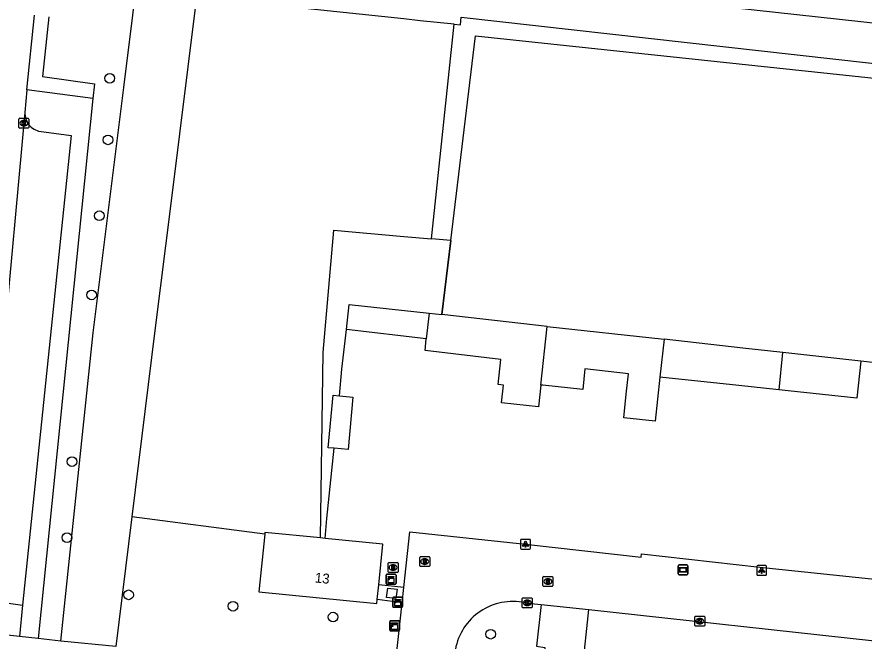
# Model space of a CAD drawing. Extents: x 162515 to 163909, y 388494 to 389773.
# Drawn here: x 162960.9 to 163046.5, y 388555.4 to 388618.6 of the extents above; entities that cross this region are included whole.
import ezdxf

# ---------------------------------------------------------------- set-up
doc = ezdxf.new("R2010")
doc.units = 0
for name, color, linetype in [('IMGEO_Boom', 7, 'Continuous'), ('IMGEO_Groenvoorziening', 7, 'Continuous'), ('IMGEO_Hek', 7, 'Continuous'), ('IMGEO_Kast', 7, 'Continuous'), ('IMGEO_Kolk', 7, 'Continuous'), ('IMGEO_Lage_trafo', 7, 'Continuous'), ('IMGEO_Lichtpunt', 7, 'Continuous'), ('IMGEO_Loofbos', 7, 'Continuous'), ('IMGEO_Pand', 7, 'Continuous'), ('IMGEO_Pand_nummerreeks', 7, 'Continuous'), ('IMGEO_Parkeervlak_open', 7, 'Continuous'), ('IMGEO_Rijbaan_lokaal_open', 7, 'Continuous'), ('IMGEO_Rioolput', 7, 'Continuous'), ('IMGEO_Terreindeel_open', 7, 'Continuous'), ('IMGEO_Verklikker', 7, 'Continuous'), ('IMGEO_Voetpad_onverhard', 7, 'Continuous'), ('IMGEO_Voetpad_open', 7, 'Continuous')]:
    doc.layers.add(name, color=color, linetype=linetype)

msp = doc.modelspace()

# ---------------------------------------------------------------- linework, layer by layer
at = {"layer": 'IMGEO_Boom'}
for centre in [(162970.262, 388612.35), (162970.081, 388606.124), (162969.213, 388598.45), (162968.421, 388590.446), (162966.439, 388573.592), (162965.943, 388565.899), (162972.163, 388560.113), (162982.721, 388558.962), (162992.839, 388557.86), (163008.769, 388556.133)]:
    msp.add_circle(centre, 0.489, dxfattribs=at)
at = {"layer": 'IMGEO_Groenvoorziening'}
for points in [[(163004.733, 388595.939), (163007.23, 388616.641), (163090.354, 388607.805), (163079.489, 388585.494)], [(163004.733, 388595.939), (163002.79, 388596.108)], [(163003.829, 388588.448), (163004.733, 388595.939)], [(162993.498, 388580.23), (162993.73, 388582.932), (162994.196, 388586.945)], [(163050.343, 388583.278), (163046.197, 388583.746)], [(162992.026, 388565.819), (162992.203, 388567.817), (162992.946, 388574.941)], [(162999.817, 388559.316), (162997.301, 388559.633)]]:
    msp.add_lwpolyline(points, dxfattribs=at)
at = {"layer": 'IMGEO_Hek'}
for points in [[(163005.069, 388617.81), (163001.65, 388618.175), (163000, 388618.351), (162979.016, 388620.588), (162976.424, 388599.705), (162974.828, 388586.841), (162972.488, 388567.987)], [(163002.79, 388596.108), (163005.069, 388617.81)], [(163004.733, 388595.939), (163003.829, 388588.448)], [(162972.488, 388567.987), (162970.86, 388554.877)]]:
    msp.add_lwpolyline(points, dxfattribs=at)
at = {"layer": 'IMGEO_Kast'}
for p, q in [((162998.198, 388561.264), (162998.198, 388562.105)), ((162998.198, 388562.105), (162998.198, 388561.264)), ((162998.273, 388562.189), (162999.114, 388562.189)), ((162999.114, 388562.189), (162998.273, 388562.189)), ((162999.198, 388562.114), (162999.198, 388561.273)), ((162999.198, 388561.273), (162999.198, 388562.114)), ((162999.123, 388561.189), (162998.282, 388561.189)), ((162998.282, 388561.189), (162999.123, 388561.189)), ((162998.868, 388558.936), (162998.868, 388559.777)), ((162998.868, 388559.777), (162998.868, 388558.936)), ((162998.943, 388559.861), (162999.784, 388559.861)), ((162999.784, 388559.861), (162998.943, 388559.861)), ((162999.868, 388559.786), (162999.868, 388558.945)), ((162999.868, 388558.945), (162999.868, 388559.786)), ((162999.793, 388558.861), (162998.952, 388558.861)), ((162998.952, 388558.861), (162999.793, 388558.861)), ((162998.563, 388556.557), (162998.563, 388557.398)), ((162998.563, 388557.398), (162998.563, 388556.557)), ((162998.638, 388557.482), (162999.479, 388557.482)), ((162999.479, 388557.482), (162998.638, 388557.482)), ((162999.563, 388557.407), (162999.563, 388556.566)), ((162999.563, 388556.566), (162999.563, 388557.407)), ((162999.488, 388556.482), (162998.647, 388556.482)), ((162998.647, 388556.482), (162999.488, 388556.482))]:
    msp.add_line(p, q, dxfattribs=at)
for points in [[(162998.393, 388561.979), (162998.993, 388561.979), (162998.993, 388561.894), (162998.393, 388561.894), (162998.393, 388561.979)], [(162998.393, 388561.804), (162998.993, 388561.804), (162998.993, 388561.315), (162998.393, 388561.315), (162998.393, 388561.804)], [(162999.063, 388559.651), (162999.663, 388559.651), (162999.663, 388559.566), (162999.063, 388559.566), (162999.063, 388559.651)], [(162999.063, 388559.476), (162999.663, 388559.476), (162999.663, 388558.987), (162999.063, 388558.987), (162999.063, 388559.476)], [(162998.758, 388557.272), (162999.358, 388557.272), (162999.358, 388557.187), (162998.758, 388557.187), (162998.758, 388557.272)], [(162998.758, 388557.097), (162999.358, 388557.097), (162999.358, 388556.608), (162998.758, 388556.608), (162998.758, 388557.097)]]:
    msp.add_lwpolyline(points, dxfattribs=at)
for centre in [(162998.477, 388561.653), (162999.147, 388559.325), (162998.842, 388556.946)]:
    msp.add_circle(centre, 0.0377, dxfattribs=at)
for centre, start, end in [((162998.276, 388562.111), 92.4484, 184.28452), ((162998.276, 388562.111), 92.4484, 184.28452), ((162999.12, 388562.111), 2.4484, 94.28452), ((162999.12, 388562.111), 2.4484, 94.28452), ((162998.276, 388561.267), 182.4484, 274.28452), ((162998.276, 388561.267), 182.4484, 274.28452), ((162999.12, 388561.267), 272.4484, 4.28452), ((162999.12, 388561.267), 272.4484, 4.28452), ((162998.946, 388559.783), 92.4484, 184.28452), ((162998.946, 388559.783), 92.4484, 184.28452), ((162999.79, 388559.783), 2.4484, 94.28452), ((162999.79, 388559.783), 2.4484, 94.28452), ((162998.946, 388558.939), 182.4484, 274.28452), ((162998.946, 388558.939), 182.4484, 274.28452), ((162999.79, 388558.939), 272.4484, 4.28452), ((162999.79, 388558.939), 272.4484, 4.28452), ((162998.641, 388557.404), 92.4484, 184.28452), ((162998.641, 388557.404), 92.4484, 184.28452), ((162999.485, 388557.404), 2.4484, 94.28452), ((162999.485, 388557.404), 2.4484, 94.28452), ((162998.641, 388556.56), 182.4484, 274.28452), ((162998.641, 388556.56), 182.4484, 274.28452), ((162999.485, 388556.56), 272.4484, 4.28452), ((162999.485, 388556.56), 272.4484, 4.28452)]:
    msp.add_arc(centre, 0.0779, start, end, dxfattribs=at)
at = {"layer": 'IMGEO_Kolk'}
for p, q in [((162961.079, 388607.383), (162961.079, 388608.235)), ((162961.154, 388608.309), (162962.006, 388608.309)), ((162961.567, 388608.089), (162961.592, 388608.089)), ((162962.08, 388608.235), (162962.08, 388607.383)), ((162962.006, 388607.309), (162961.154, 388607.309)), ((162961.59, 388607.529), (162961.565, 388607.529)), ((163011.965, 388558.876), (163011.965, 388559.728)), ((163012.04, 388559.802), (163012.892, 388559.802)), ((163012.966, 388559.728), (163012.966, 388558.876)), ((163012.476, 388559.022), (163012.451, 388559.022)), ((163012.453, 388559.582), (163012.478, 388559.582)), ((163012.892, 388558.802), (163012.04, 388558.802)), ((163029.411, 388557.023), (163029.411, 388557.875)), ((163029.486, 388557.949), (163030.338, 388557.949)), ((163029.922, 388557.169), (163029.897, 388557.169)), ((163029.899, 388557.729), (163029.924, 388557.729)), ((163030.412, 388557.875), (163030.412, 388557.023)), ((163030.338, 388556.949), (163029.486, 388556.949))]:
    msp.add_line(p, q, dxfattribs=at)
for points in [[(162961.079, 388607.383), (162961.079, 388608.235)], [(162961.154, 388608.309), (162962.006, 388608.309)], [(162961.4, 388608.009), (162961.523, 388608.009), (162961.523, 388607.858), (162961.653, 388608.009), (162961.817, 388608.009), (162961.671, 388607.858), (162961.824, 388607.609), (162961.672, 388607.609), (162961.587, 388607.773), (162961.523, 388607.706), (162961.523, 388607.609), (162961.4, 388607.609), (162961.4, 388608.009)], [(162962.08, 388608.235), (162962.08, 388607.383)], [(162962.006, 388607.309), (162961.154, 388607.309)], [(163011.965, 388558.876), (163011.965, 388559.728)], [(163012.04, 388559.802), (163012.892, 388559.802)], [(163012.966, 388559.728), (163012.966, 388558.876)], [(163012.286, 388559.502), (163012.409, 388559.502), (163012.409, 388559.351), (163012.539, 388559.502), (163012.703, 388559.502), (163012.557, 388559.351), (163012.71, 388559.102), (163012.558, 388559.102), (163012.473, 388559.266), (163012.409, 388559.199), (163012.409, 388559.102), (163012.286, 388559.102), (163012.286, 388559.502)], [(163012.892, 388558.802), (163012.04, 388558.802)], [(163029.411, 388557.023), (163029.411, 388557.875)], [(163029.486, 388557.949), (163030.338, 388557.949)], [(163029.732, 388557.649), (163029.855, 388557.649), (163029.855, 388557.498), (163029.985, 388557.649), (163030.149, 388557.649), (163030.003, 388557.498), (163030.156, 388557.249), (163030.004, 388557.249), (163029.919, 388557.413), (163029.855, 388557.346), (163029.855, 388557.249), (163029.732, 388557.249), (163029.732, 388557.649)], [(163030.412, 388557.875), (163030.412, 388557.023)], [(163030.338, 388556.949), (163029.486, 388556.949)]]:
    msp.add_lwpolyline(points, dxfattribs=at)
for centre, start, end in [((162961.156, 388608.233), 91.55205, 178.44795), ((162961.156, 388608.233), 91.55205, 178.44795), ((162962.004, 388608.233), 1.55205, 88.44795), ((162962.004, 388608.233), 1.55205, 88.44795), ((162961.156, 388607.385), 181.55205, 268.44795), ((162961.156, 388607.385), 181.55205, 268.44795), ((162962.004, 388607.385), 271.55205, 358.44795), ((162962.004, 388607.385), 271.55205, 358.44795), ((163012.042, 388559.726), 91.55205, 178.44795), ((163012.042, 388559.726), 91.55205, 178.44795), ((163012.89, 388559.726), 1.55205, 88.44795), ((163012.89, 388559.726), 1.55205, 88.44795), ((163012.042, 388558.878), 181.55205, 268.44795), ((163012.042, 388558.878), 181.55205, 268.44795), ((163012.89, 388558.878), 271.55205, 358.44795), ((163012.89, 388558.878), 271.55205, 358.44795), ((163029.488, 388557.873), 91.55205, 178.44795), ((163029.488, 388557.873), 91.55205, 178.44795), ((163030.336, 388557.873), 1.55205, 88.44795), ((163030.336, 388557.873), 1.55205, 88.44795), ((163029.488, 388557.025), 181.55205, 268.44795), ((163029.488, 388557.025), 181.55205, 268.44795), ((163030.336, 388557.025), 271.55205, 358.44795), ((163030.336, 388557.025), 271.55205, 358.44795)]:
    msp.add_arc(centre, 0.0765, start, end, dxfattribs=at)
for centre, major_axis, ratio, start_param, end_param in [((162961.566, 388607.809), (-0.387, 0.002), 0.722429, 4.712389, 7.853982), ((162961.591, 388607.809), (-0.39, 0.002), 0.717154, 1.570796, 4.712389), ((163012.452, 388559.302), (-0.387, 0.002), 0.722429, 4.712389, 7.853982), ((163012.477, 388559.302), (-0.39, 0.002), 0.717154, 1.570796, 4.712389), ((163029.898, 388557.449), (-0.387, 0.002), 0.722429, 4.712389, 7.853982), ((163029.923, 388557.449), (-0.39, 0.002), 0.717154, 1.570796, 4.712389)]:
    msp.add_ellipse(centre, major_axis=major_axis, ratio=ratio, start_param=start_param, end_param=end_param, dxfattribs=at)
at = {"layer": 'IMGEO_Lage_trafo'}
msp.add_lwpolyline([(162999.194, 388559.753), (162998.254, 388559.859), (162998.36, 388560.799), (162999.3, 388560.693), (162999.194, 388559.753)], dxfattribs=at)
at = {"layer": 'IMGEO_Lichtpunt'}
for p, q in [((163012.692, 388565.722), (163011.884, 388565.722)), ((163012.692, 388565.722), (163011.884, 388565.722)), ((163011.79, 388565.627), (163011.79, 388564.82)), ((163011.79, 388565.627), (163011.79, 388564.82)), ((163012.786, 388564.82), (163012.786, 388565.627)), ((163012.786, 388564.82), (163012.786, 388565.627)), ((163011.884, 388564.726), (163012.692, 388564.726)), ((163011.884, 388564.726), (163012.692, 388564.726)), ((163035.667, 388562.988), (163035.667, 388562.181)), ((163035.667, 388562.988), (163035.667, 388562.181)), ((163036.569, 388563.083), (163035.761, 388563.083)), ((163036.569, 388563.083), (163035.761, 388563.083)), ((163036.663, 388562.181), (163036.663, 388562.988)), ((163036.663, 388562.181), (163036.663, 388562.988)), ((163035.761, 388562.087), (163036.569, 388562.087)), ((163035.761, 388562.087), (163036.569, 388562.087))]:
    msp.add_line(p, q, dxfattribs=at)
for points in [[(163012.164, 388565.291), (163012.203, 388565.263), (163012.015, 388565.001), (163011.977, 388565.028), (163012.164, 388565.291)], [(163012.266, 388565.243), (163012.313, 388565.243), (163012.313, 388564.921), (163012.266, 388564.921), (163012.266, 388565.243)], [(163012.376, 388565.263), (163012.414, 388565.29), (163012.601, 388565.028), (163012.562, 388565), (163012.376, 388565.263)], [(163036.041, 388562.652), (163036.08, 388562.624), (163035.892, 388562.362), (163035.854, 388562.389), (163036.041, 388562.652)], [(163036.143, 388562.604), (163036.19, 388562.604), (163036.19, 388562.282), (163036.143, 388562.282), (163036.143, 388562.604)], [(163036.253, 388562.624), (163036.291, 388562.651), (163036.478, 388562.389), (163036.439, 388562.361), (163036.253, 388562.624)]]:
    msp.add_lwpolyline(points, dxfattribs=at)
for centre in [(163012.289, 388565.425), (163036.166, 388562.786)]:
    msp.add_circle(centre, 0.0994, dxfattribs=at)
for centre, start, end in [((163011.884, 388565.627), 90, 180), ((163011.884, 388565.627), 90, 180), ((163012.692, 388565.627), 0, 90), ((163012.692, 388565.627), 0, 90), ((163011.884, 388564.82), 180, 270), ((163011.884, 388564.82), 180, 270), ((163012.692, 388564.82), 270, 0), ((163012.692, 388564.82), 270, 360), ((163035.761, 388562.988), 90, 180), ((163035.761, 388562.988), 90, 180), ((163036.569, 388562.988), 0, 90), ((163036.569, 388562.988), 0, 90), ((163035.761, 388562.181), 180, 270), ((163035.761, 388562.181), 180, 270), ((163036.569, 388562.181), 270, 0), ((163036.569, 388562.181), 270, 360)]:
    msp.add_arc(centre, 0.0946, start, end, dxfattribs=at)
at = {"layer": 'IMGEO_Loofbos'}
for points in [[(162964.118, 388618.562), (162963.448, 388612.545), (162968.731, 388611.807), (162968.549, 388610.318)], [(163002.79, 388596.108), (163005.069, 388617.81)], [(162991.571, 388565.865), (162991.826, 388584.623), (162992.929, 388596.983), (163000, 388596.356), (163002.79, 388596.108)], [(162985.926, 388566.254), (162972.488, 388567.987)]]:
    msp.add_lwpolyline(points, dxfattribs=at)
at = {"layer": 'IMGEO_Pand'}
for points in [[(162994.196, 388586.945), (162994.478, 388589.486), (163002.555, 388588.59)], [(163002.555, 388588.59), (163002.264, 388586.008)], [(163002.555, 388588.59), (163003.829, 388588.448)], [(163014.493, 388587.265), (163003.829, 388588.448)], [(163013.84, 388581.331), (163014.493, 388587.265)], [(163014.493, 388587.265), (163026.294, 388585.955)], [(163002.264, 388586.008), (162994.196, 388586.945)], [(163013.84, 388581.331), (163013.598, 388579.132), (163009.859, 388579.527), (163010.049, 388581.324), (163009.52, 388581.38), (163009.789, 388583.926), (163002.132, 388584.836), (163002.264, 388586.008)], [(163026.294, 388585.955), (163025.885, 388582.139)], [(163038.315, 388584.621), (163034.251, 388585.072), (163026.294, 388585.955)], [(163037.931, 388580.847), (163038.315, 388584.621)], [(163046.197, 388583.746), (163038.315, 388584.621)], [(163046.197, 388583.746), (163045.793, 388579.998), (163038.848, 388580.748), (163037.931, 388580.847)], [(163025.885, 388582.139), (163025.405, 388577.665), (163022.214, 388578.016), (163022.476, 388580.395), (163022.704, 388582.469), (163018.301, 388582.953), (163018.071, 388580.865), (163014.052, 388581.308), (163013.84, 388581.331)], [(163037.931, 388580.847), (163037.908, 388580.849), (163033.849, 388581.284), (163025.885, 388582.139)], [(162992.946, 388574.941), (162992.355, 388574.994), (162992.829, 388580.29), (162993.498, 388580.23)], [(162993.498, 388580.23), (162994.821, 388580.112), (162994.347, 388574.816), (162992.946, 388574.941)], [(162985.926, 388566.254), (162985.319, 388560.432), (162997.261, 388559.233), (162997.301, 388559.633)], [(162991.571, 388565.865), (162985.944, 388566.429), (162985.926, 388566.254)], [(162992.026, 388565.819), (162991.571, 388565.865)], [(162997.448, 388561.109), (162997.858, 388565.235), (162992.026, 388565.819)], [(162997.301, 388559.633), (162997.448, 388561.109)]]:
    msp.add_lwpolyline(points, dxfattribs=at)
at = {"layer": 'IMGEO_Parkeervlak_open'}
msp.add_lwpolyline([(162958.379, 388559.517), (162961.44, 388559.076)], dxfattribs=at)
at = {"layer": 'IMGEO_Rijbaan_lokaal_open'}
for points in [[(162961.889, 388611.173), (162962.649, 388618.722)], [(162961.889, 388611.173), (162961.68, 388608.905)], [(162961.68, 388608.905), (162959.411, 388584.283), (162956.595, 388558.931)], [(162999.987, 388560.86), (163000.607, 388566.496), (163012.283, 388565.224), (163023.98, 388563.913), (163024.016, 388564.261), (163035.984, 388562.926), (163047.901, 388561.655), (163059.732, 388560.275)], [(162999.817, 388559.316), (162999.987, 388560.86)], [(162998.998, 388551.886), (162999.817, 388559.316)], [(163012.22, 388559.314), (163013.862, 388559.137)], [(163013.862, 388559.137), (163018.69, 388558.618)], [(163018.69, 388558.618), (163047.561, 388555.463)]]:
    msp.add_lwpolyline(points, dxfattribs=at)
msp.add_arc((163011.007, 388553.534), 5.906, 78.15108, 169.67972, dxfattribs=at)
at = {"layer": 'IMGEO_Rioolput'}
for p, q in [((162998.401, 388562.454), (162998.401, 388563.306)), ((162998.476, 388563.38), (162999.328, 388563.38)), ((162998.889, 388563.16), (162998.914, 388563.16)), ((162999.402, 388563.306), (162999.402, 388562.454)), ((163001.607, 388563.05), (163001.607, 388563.902)), ((163001.682, 388563.976), (163002.534, 388563.976)), ((163002.118, 388563.196), (163002.093, 388563.196)), ((163002.095, 388563.756), (163002.12, 388563.756)), ((163002.608, 388563.902), (163002.608, 388563.05)), ((162999.328, 388562.38), (162998.476, 388562.38)), ((162998.912, 388562.6), (162998.887, 388562.6)), ((163002.534, 388562.976), (163001.682, 388562.976)), ((163014.054, 388561.042), (163014.054, 388561.894)), ((163014.129, 388561.968), (163014.981, 388561.968)), ((163014.542, 388561.748), (163014.567, 388561.748)), ((163015.055, 388561.894), (163015.055, 388561.042)), ((163014.981, 388560.968), (163014.129, 388560.968)), ((163014.565, 388561.188), (163014.54, 388561.188))]:
    msp.add_line(p, q, dxfattribs=at)
for points in [[(162998.401, 388562.454), (162998.401, 388563.306)], [(162998.476, 388563.38), (162999.328, 388563.38)], [(162999.402, 388563.306), (162999.402, 388562.454)], [(163001.607, 388563.05), (163001.607, 388563.902)], [(163001.682, 388563.976), (163002.534, 388563.976)], [(163002.196, 388563.674), (163001.944, 388563.676), (163001.944, 388563.276)], [(163001.944, 388563.276), (163002.068, 388563.276), (163002.068, 388563.438), (163002.079, 388563.438)], [(163002.122, 388563.595), (163002.068, 388563.595), (163002.068, 388563.514)], [(163002.068, 388563.514), (163002.12, 388563.514)], [(163002.126, 388563.409), (163002.197, 388563.276), (163002.337, 388563.276), (163002.272, 388563.402)], [(163002.608, 388563.902), (163002.608, 388563.05)], [(162999.328, 388562.38), (162998.476, 388562.38)], [(162998.99, 388563.078), (162998.738, 388563.08), (162998.738, 388562.68)], [(162998.738, 388562.68), (162998.862, 388562.68), (162998.862, 388562.842), (162998.873, 388562.842)], [(162998.916, 388562.999), (162998.862, 388562.999), (162998.862, 388562.918)], [(162998.862, 388562.918), (162998.914, 388562.918)], [(162998.92, 388562.813), (162998.991, 388562.68), (162999.131, 388562.68), (162999.066, 388562.806)], [(163002.534, 388562.976), (163001.682, 388562.976)], [(163014.054, 388561.042), (163014.054, 388561.894)], [(163014.129, 388561.968), (163014.981, 388561.968)], [(163014.643, 388561.666), (163014.391, 388561.668), (163014.391, 388561.268)], [(163014.391, 388561.268), (163014.515, 388561.268), (163014.515, 388561.43), (163014.526, 388561.43)], [(163014.569, 388561.587), (163014.515, 388561.587), (163014.515, 388561.506)], [(163014.515, 388561.506), (163014.567, 388561.506)], [(163015.055, 388561.894), (163015.055, 388561.042)], [(163014.981, 388560.968), (163014.129, 388560.968)], [(163014.573, 388561.401), (163014.644, 388561.268), (163014.784, 388561.268), (163014.719, 388561.394)]]:
    msp.add_lwpolyline(points, dxfattribs=at)
for centre, radius, start, end in [((162998.478, 388563.304), 0.0765, 91.55205, 178.44795), ((162998.478, 388563.304), 0.0765, 91.55205, 178.44795), ((162999.326, 388563.304), 0.0765, 1.55205, 88.44795), ((162999.326, 388563.304), 0.0765, 1.55205, 88.44795), ((163001.684, 388563.9), 0.0765, 91.55205, 178.44795), ((163001.684, 388563.9), 0.0765, 91.55205, 178.44795), ((163002.078, 388563.385), 0.0533, 26.02933, 88.69889), ((163002.104, 388563.703), 0.19, 274.7715, 282.96867), ((163002.128, 388563.499), 0.0964, 77.00612, 93.18647), ((163002.142, 388563.556), 0.0378, 276.66336, 79.67722), ((163002.195, 388563.564), 0.109, 350.36119, 89.41601), ((163002.193, 388563.564), 0.112, 277.58423, 350.98172), ((163002.177, 388563.349), 0.108, 29.51342, 73.79051), ((163002.532, 388563.9), 0.0765, 1.55205, 88.44795), ((163002.532, 388563.9), 0.0765, 1.55205, 88.44795), ((162998.478, 388562.456), 0.0765, 181.55205, 268.44795), ((162998.478, 388562.456), 0.0765, 181.55205, 268.44795), ((162998.872, 388562.789), 0.0533, 26.02933, 88.69889), ((162998.898, 388563.107), 0.19, 274.7715, 282.96867), ((162998.922, 388562.903), 0.0964, 77.00612, 93.18647), ((162998.936, 388562.96), 0.0378, 276.66336, 79.67722), ((162998.989, 388562.968), 0.109, 350.36119, 89.41601), ((162998.987, 388562.968), 0.112, 277.58423, 350.98172), ((162998.971, 388562.753), 0.108, 29.51342, 73.79051), ((162999.326, 388562.456), 0.0765, 271.55205, 358.44795), ((162999.326, 388562.456), 0.0765, 271.55205, 358.44795), ((163001.684, 388563.052), 0.0765, 181.55205, 268.44795), ((163001.684, 388563.052), 0.0765, 181.55205, 268.44795), ((163002.532, 388563.052), 0.0765, 271.55205, 358.44795), ((163002.532, 388563.052), 0.0765, 271.55205, 358.44795), ((163014.131, 388561.892), 0.0765, 91.55205, 178.44795), ((163014.131, 388561.892), 0.0765, 91.55205, 178.44795), ((163014.525, 388561.377), 0.0533, 26.02933, 88.69889), ((163014.551, 388561.695), 0.19, 274.7715, 282.96867), ((163014.575, 388561.491), 0.0964, 77.00612, 93.18647), ((163014.589, 388561.548), 0.0378, 276.66336, 79.67722), ((163014.642, 388561.556), 0.109, 350.36119, 89.41601), ((163014.64, 388561.556), 0.112, 277.58423, 350.98172), ((163014.624, 388561.341), 0.108, 29.51342, 73.79051), ((163014.979, 388561.892), 0.0765, 1.55205, 88.44795), ((163014.979, 388561.892), 0.0765, 1.55205, 88.44795), ((163014.131, 388561.044), 0.0765, 181.55205, 268.44795), ((163014.131, 388561.044), 0.0765, 181.55205, 268.44795), ((163014.979, 388561.044), 0.0765, 271.55205, 358.44795), ((163014.979, 388561.044), 0.0765, 271.55205, 358.44795)]:
    msp.add_arc(centre, radius, start, end, dxfattribs=at)
for centre, major_axis, ratio, start_param, end_param in [((162998.888, 388562.88), (-0.387, 0.002), 0.722429, 4.712389, 7.853982), ((162998.913, 388562.88), (-0.39, 0.002), 0.717154, 1.570796, 4.712389), ((163002.094, 388563.476), (-0.387, 0.002), 0.722429, 4.712389, 7.853982), ((163002.119, 388563.476), (-0.39, 0.002), 0.717154, 1.570796, 4.712389), ((163014.541, 388561.468), (-0.387, 0.002), 0.722429, 4.712389, 7.853982), ((163014.566, 388561.468), (-0.39, 0.002), 0.717154, 1.570796, 4.712389)]:
    msp.add_ellipse(centre, major_axis=major_axis, ratio=ratio, start_param=start_param, end_param=end_param, dxfattribs=at)
at = {"layer": 'IMGEO_Terreindeel_open'}
msp.add_lwpolyline([(162999.987, 388560.86), (162997.448, 388561.109)], dxfattribs=at)
at = {"layer": 'IMGEO_Verklikker'}
for p, q in [((163027.812, 388563.146), (163028.602, 388563.146)), ((163028.602, 388563.146), (163027.812, 388563.146)), ((163027.712, 388562.246), (163027.712, 388563.046)), ((163027.712, 388563.046), (163027.712, 388562.246)), ((163028.702, 388563.046), (163028.702, 388562.246)), ((163028.702, 388562.246), (163028.702, 388563.046)), ((163028.602, 388562.146), (163027.812, 388562.146)), ((163027.812, 388562.146), (163028.602, 388562.146))]:
    msp.add_line(p, q, dxfattribs=at)
for points in [[(163027.813, 388562.878), (163028.601, 388562.878), (163028.601, 388562.414), (163027.813, 388562.414), (163027.813, 388562.878)], [(163027.878, 388562.813), (163027.878, 388562.479), (163028.536, 388562.479), (163028.536, 388562.813), (163027.878, 388562.813)]]:
    msp.add_lwpolyline(points, dxfattribs=at)
for centre, start, end in [((163027.812, 388563.046), 90, 180), ((163027.812, 388563.046), 90, 180), ((163028.602, 388563.046), 0, 90), ((163028.602, 388563.046), 360, 90), ((163027.812, 388562.246), 180, 270), ((163027.812, 388562.246), 180, 270), ((163028.602, 388562.246), 270, 0), ((163028.602, 388562.246), 270, 0)]:
    msp.add_arc(centre, 0.1, start, end, dxfattribs=at)
at = {"layer": 'IMGEO_Voetpad_onverhard'}
for points in [[(162965.32, 388555.442), (162968.591, 388586.594), (162971.679, 388611.418), (162973.501, 388626.071), (163066.203, 388615.891), (163091.913, 388612.689), (163095.764, 388613.06)], [(163005.069, 388617.81), (163001.65, 388618.175), (163000, 388618.351), (162979.016, 388620.588), (162976.424, 388599.705), (162974.828, 388586.841), (162972.488, 388567.987)], [(163005.069, 388617.81), (163005.707, 388617.745), (163005.799, 388618.536), (163092.645, 388608.787)], [(162972.488, 388567.987), (162970.86, 388554.877)]]:
    msp.add_lwpolyline(points, dxfattribs=at)
at = {"layer": 'IMGEO_Voetpad_open'}
for points in [[(162968.549, 388610.318), (162961.889, 388611.173)], [(162968.549, 388610.318), (162963.018, 388555.695)], [(162961.68, 388608.905), (162961.681, 388608.736), (162961.697, 388608.568), (162961.728, 388608.402), (162961.774, 388608.239), (162961.834, 388608.081), (162961.908, 388607.929), (162961.995, 388607.785), (162962.095, 388607.648), (162962.206, 388607.521), (162962.329, 388607.405), (162962.461, 388607.3), (162962.602, 388607.207), (162962.751, 388607.127), (162962.907, 388607.061), (162963.067, 388607.009), (162963.09, 388607.003), (162966.344, 388606.55), (162961.44, 388559.076)], [(162961.44, 388559.076), (162961.128, 388555.903)], [(163013.862, 388559.137), (163013.404, 388554.928), (163014.233, 388554.771), (163014.124, 388552.987), (163018.036, 388552.566), (163018.69, 388558.618)], [(162961.128, 388555.903), (162956.286, 388556.441)], [(162963.018, 388555.695), (162961.128, 388555.903)], [(162965.32, 388555.442), (162963.018, 388555.695)], [(162970.86, 388554.877), (162965.32, 388555.442)]]:
    msp.add_lwpolyline(points, dxfattribs=at)

# ---------------------------------------------------------------- texts
at = {"layer": 'IMGEO_Pand_nummerreeks'}
msp.add_text('13', height=1, rotation=354.26469, dxfattribs=at).set_placement((162990.957, 388561.374))

doc.saveas('drawing.dxf')
